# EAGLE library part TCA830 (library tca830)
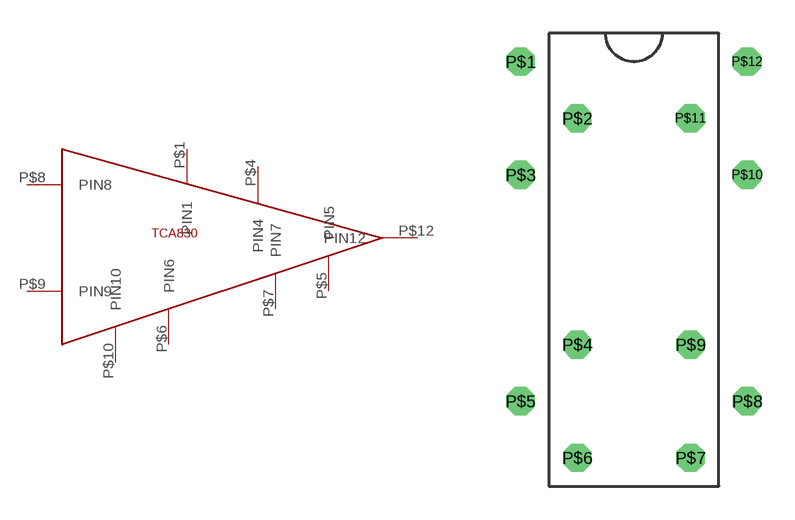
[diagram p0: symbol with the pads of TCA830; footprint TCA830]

Designator prefix -

## TCA830  [TCA830]
P$1  PIN1
P$4  PIN4
P$5  PIN5
P$6  PIN6
P$7  PIN7
P$8  PIN8
P$9  PIN9
P$10  PIN10
P$12  PIN12

## Footprint TCA830 (pad centres in mm)
drill 0.5 pad 1.27 octagon: P$1 10.16,17.78; P$2 12.7,15.24; P$3 10.16,12.7; P$4 12.7,5.08; P$5 10.16,2.54; P$6 12.7,0; P$7 17.78,0; P$8 20.32,2.54; P$9 17.78,5.08; P$10 20.32,12.7; P$11 17.78,15.24; P$12 20.32,17.78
